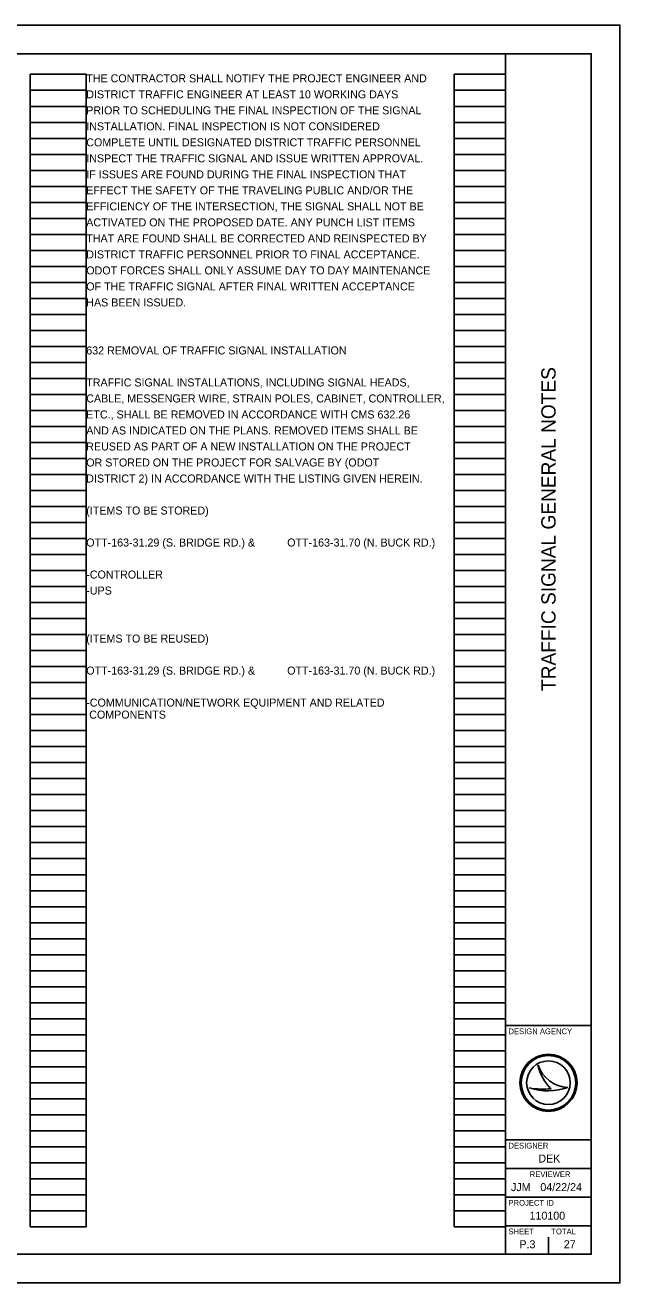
# Model space of a CAD drawing. Extents: x 26.5 to 76, y -1.6 to 20.4.
# Drawn here: x 65.56 to 75.97, y -1.61 to 20.39 of the extents above; entities that cross this region are included whole.
import ezdxf

# ---------------------------------------------------------------- set-up
doc = ezdxf.new("R2010")
doc.units = 0
for name, color, linetype in [('SH_Border', 7, 'Continuous'), ('SH_Cut_Line', 7, 'Continuous'), ('SH_Data', 7, 'Continuous'), ('SH_Text', 7, 'Continuous')]:
    doc.layers.add(name, color=color, linetype=linetype)

msp = doc.modelspace()

# ---------------------------------------------------------------- linework, layer by layer
at = {"layer": 'SH_Border'}
for p, q in [((73.967, -1.109), (73.967, 19.891)), ((73.967, 2.891), (75.467, 2.891)), ((73.967, 0.891), (75.467, 0.891)), ((73.967, 0.391), (75.467, 0.391)), ((73.967, -0.109), (75.467, -0.109)), ((73.967, -0.609), (75.467, -0.609))]:
    msp.add_line(p, q, dxfattribs=at)
msp.add_lwpolyline([(43.467, 19.891), (75.467, 19.891), (75.467, -1.109), (43.467, -1.109)], close=True, dxfattribs=at)
at = {"layer": 'SH_Cut_Line'}
msp.add_lwpolyline([(41.967, -1.609), (75.967, -1.609), (75.967, 20.391), (41.967, 20.391)], close=True, dxfattribs=at)
at = {"layer": 'SH_Data'}
for p, q in [((65.647, -0.629), (65.647, 19.531)), ((65.647, 19.531), (66.627, 19.531)), ((66.627, -0.629), (66.627, 19.531)), ((73.067, -0.629), (73.067, 19.531)), ((73.067, 19.531), (73.967, 19.531)), ((73.967, -0.629), (73.967, 19.531)), ((65.647, 19.251), (66.627, 19.251)), ((73.067, 19.251), (73.967, 19.251)), ((65.647, 18.971), (66.627, 18.971)), ((73.067, 18.971), (73.967, 18.971)), ((65.647, 18.691), (66.627, 18.691)), ((73.067, 18.691), (73.967, 18.691)), ((65.647, 18.411), (66.627, 18.411)), ((73.067, 18.411), (73.967, 18.411)), ((65.647, 18.131), (66.627, 18.131)), ((73.067, 18.131), (73.967, 18.131)), ((65.647, 17.851), (66.627, 17.851)), ((73.067, 17.851), (73.967, 17.851)), ((65.647, 17.571), (66.627, 17.571)), ((73.067, 17.571), (73.967, 17.571)), ((65.647, 17.291), (66.627, 17.291)), ((73.067, 17.291), (73.967, 17.291)), ((65.647, 17.011), (66.627, 17.011)), ((73.067, 17.011), (73.967, 17.011)), ((65.647, 16.731), (66.627, 16.731)), ((73.067, 16.731), (73.967, 16.731)), ((65.647, 16.451), (66.627, 16.451)), ((73.067, 16.451), (73.967, 16.451)), ((65.647, 16.171), (66.627, 16.171)), ((73.067, 16.171), (73.967, 16.171)), ((65.647, 15.891), (66.627, 15.891)), ((73.067, 15.891), (73.967, 15.891)), ((65.647, 15.611), (66.627, 15.611)), ((73.067, 15.611), (73.967, 15.611)), ((65.647, 15.331), (66.627, 15.331)), ((73.067, 15.331), (73.967, 15.331)), ((65.647, 15.051), (66.627, 15.051)), ((73.067, 15.051), (73.967, 15.051)), ((65.647, 14.771), (66.627, 14.771)), ((73.067, 14.771), (73.967, 14.771)), ((65.647, 14.491), (66.627, 14.491)), ((73.067, 14.491), (73.967, 14.491)), ((65.647, 14.211), (66.627, 14.211)), ((73.067, 14.211), (73.967, 14.211)), ((65.647, 13.931), (66.627, 13.931)), ((73.067, 13.931), (73.967, 13.931)), ((65.647, 13.651), (66.627, 13.651)), ((73.067, 13.651), (73.967, 13.651)), ((65.647, 13.371), (66.627, 13.371)), ((73.067, 13.371), (73.967, 13.371)), ((65.647, 13.091), (66.627, 13.091)), ((73.067, 13.091), (73.967, 13.091)), ((65.647, 12.811), (66.627, 12.811)), ((73.067, 12.811), (73.967, 12.811)), ((65.647, 12.531), (66.627, 12.531)), ((73.067, 12.531), (73.967, 12.531)), ((65.647, 12.251), (66.627, 12.251)), ((73.067, 12.251), (73.967, 12.251)), ((65.647, 11.971), (66.627, 11.971)), ((73.067, 11.971), (73.967, 11.971)), ((65.647, 11.691), (66.627, 11.691)), ((73.067, 11.691), (73.967, 11.691)), ((65.647, 11.411), (66.627, 11.411)), ((73.067, 11.411), (73.967, 11.411)), ((65.647, 11.131), (66.627, 11.131)), ((73.067, 11.131), (73.967, 11.131)), ((65.647, 10.851), (66.627, 10.851)), ((73.067, 10.851), (73.967, 10.851)), ((65.647, 10.571), (66.627, 10.571)), ((73.067, 10.571), (73.967, 10.571)), ((65.647, 10.291), (66.627, 10.291)), ((73.067, 10.291), (73.967, 10.291)), ((65.647, 10.011), (66.627, 10.011)), ((73.067, 10.011), (73.967, 10.011)), ((65.647, 9.731), (66.627, 9.731)), ((73.067, 9.731), (73.967, 9.731)), ((65.647, 9.451), (66.627, 9.451)), ((73.067, 9.451), (73.967, 9.451)), ((65.647, 9.171), (66.627, 9.171)), ((73.067, 9.171), (73.967, 9.171)), ((65.647, 8.891), (66.627, 8.891)), ((73.067, 8.891), (73.967, 8.891)), ((65.647, 8.611), (66.627, 8.611)), ((73.067, 8.611), (73.967, 8.611)), ((65.647, 8.331), (66.627, 8.331)), ((73.067, 8.331), (73.967, 8.331)), ((65.647, 8.051), (66.627, 8.051)), ((73.067, 8.051), (73.967, 8.051)), ((65.647, 7.771), (66.627, 7.771)), ((73.067, 7.771), (73.967, 7.771)), ((65.647, 7.491), (66.627, 7.491)), ((73.067, 7.491), (73.967, 7.491)), ((65.647, 7.211), (66.627, 7.211)), ((73.067, 7.211), (73.967, 7.211)), ((65.647, 6.931), (66.627, 6.931)), ((73.067, 6.931), (73.967, 6.931)), ((65.647, 6.651), (66.627, 6.651)), ((73.067, 6.651), (73.967, 6.651)), ((65.647, 6.371), (66.627, 6.371)), ((73.067, 6.371), (73.967, 6.371)), ((65.647, 6.091), (66.627, 6.091)), ((73.067, 6.091), (73.967, 6.091)), ((65.647, 5.811), (66.627, 5.811)), ((73.067, 5.811), (73.967, 5.811)), ((65.647, 5.531), (66.627, 5.531)), ((73.067, 5.531), (73.967, 5.531)), ((65.647, 5.251), (66.627, 5.251)), ((73.067, 5.251), (73.967, 5.251)), ((65.647, 4.971), (66.627, 4.971)), ((73.067, 4.971), (73.967, 4.971)), ((65.647, 4.691), (66.627, 4.691)), ((73.067, 4.691), (73.967, 4.691)), ((65.647, 4.411), (66.627, 4.411)), ((73.067, 4.411), (73.967, 4.411)), ((65.647, 4.131), (66.627, 4.131)), ((73.067, 4.131), (73.967, 4.131)), ((65.647, 3.851), (66.627, 3.851)), ((73.067, 3.851), (73.967, 3.851)), ((65.647, 3.571), (66.627, 3.571)), ((73.067, 3.571), (73.967, 3.571)), ((65.647, 3.291), (66.627, 3.291)), ((73.067, 3.291), (73.967, 3.291)), ((65.647, 3.011), (66.627, 3.011)), ((73.067, 3.011), (73.967, 3.011)), ((65.647, 2.731), (66.627, 2.731)), ((73.067, 2.731), (73.967, 2.731)), ((65.647, 2.451), (66.627, 2.451)), ((73.067, 2.451), (73.967, 2.451)), ((74.534, 2.201), (74.534, 2.201)), ((65.647, 2.171), (66.627, 2.171)), ((73.067, 2.171), (73.967, 2.171)), ((65.647, 1.891), (66.627, 1.891)), ((73.067, 1.891), (73.967, 1.891)), ((74.384, 1.801), (74.384, 1.801)), ((74.717, 1.891), (74.717, 1.891)), ((75.054, 1.81), (75.054, 1.81)), ((65.647, 1.611), (66.627, 1.611)), ((73.067, 1.611), (73.967, 1.611)), ((65.647, 1.331), (66.627, 1.331)), ((73.067, 1.331), (73.967, 1.331)), ((65.647, 1.051), (66.627, 1.051)), ((73.067, 1.051), (73.967, 1.051)), ((65.647, 0.771), (66.627, 0.771)), ((73.067, 0.771), (73.967, 0.771)), ((65.647, 0.491), (66.627, 0.491)), ((73.067, 0.491), (73.967, 0.491)), ((65.647, 0.211), (66.627, 0.211)), ((73.067, 0.211), (73.967, 0.211)), ((65.647, -0.069), (66.627, -0.069)), ((73.067, -0.069), (73.967, -0.069)), ((65.647, -0.349), (66.627, -0.349)), ((73.067, -0.349), (73.967, -0.349)), ((65.647, -0.629), (66.627, -0.629)), ((73.067, -0.629), (73.967, -0.629)), ((74.717, -1.109), (74.717, -0.809)), ((74.342, -0.934), (74.342, -0.934))]:
    msp.add_line(p, q, dxfattribs=at)
for radius in [0.5, 0.477, 0.477, 0.382]:
    msp.add_circle((74.717, 1.891), radius, dxfattribs=at)
for centre, radius, start, end in [((75.083, 2.389), 0.58, 198.9257, 198.9319), ((75.313, 2.361), 0.796, 191.6379, 191.6421), ((75.083, 2.389), 0.58, 198.9319, 267.1657), ((75.313, 2.361), 0.796, 191.6421, 226.0947), ((74.706, 2.761), 1.013, 251.4576, 290.0832), ((74.615, 3.045), 1.266, 259.4964, 259.4995), ((74.706, 2.761), 1.013, 251.4527, 251.4576), ((74.615, 3.045), 1.266, 259.4995, 276.6672)]:
    msp.add_arc(centre, radius, start, end, dxfattribs=at)

# ---------------------------------------------------------------- texts
msp.add_text('TRAFFIC SIGNAL GENERAL NOTES', height=0.25, rotation=90, dxfattribs=at).set_placement((74.842, 8.744))
for s, height, p in [('DESIGN AGENCY', 0.1, (74.017, 2.741)), ('DESIGNER', 0.1, (74.017, 0.741)), ('DEK', 0.14, (74.54, 0.496)), ('REVIEWER', 0.1, (74.389, 0.241)), ('JJM', 0.14, (74.061, -0.004)), ('04/22/24', 0.14, (74.575, -0.004)), ('PROJECT ID', 0.1, (74.017, -0.259)), ('110100', 0.14, (74.385, -0.504)), ('SHEET', 0.1, (74.017, -0.759)), ('TOTAL', 0.1, (74.767, -0.759)), ('P.3', 0.14, (74.208, -1.004)), ('27', 0.14, (74.985, -1.004))]:
    msp.add_text(s, height=height, dxfattribs=at).set_placement(p)
at = {"layer": 'SH_Text'}
for s, p in [('THE CONTRACTOR SHALL NOTIFY THE PROJECT ENGINEER AND', (66.627, 19.391)), ('DISTRICT TRAFFIC ENGINEER AT LEAST 10 WORKING DAYS', (66.627, 19.111)), ('PRIOR TO SCHEDULING THE FINAL INSPECTION OF THE SIGNAL', (66.627, 18.831)), ('INSTALLATION. FINAL INSPECTION IS NOT CONSIDERED', (66.627, 18.551)), ('COMPLETE UNTIL DESIGNATED DISTRICT TRAFFIC PERSONNEL', (66.627, 18.271)), ('INSPECT THE TRAFFIC SIGNAL AND ISSUE WRITTEN APPROVAL.', (66.627, 17.991)), ('IF ISSUES ARE FOUND DURING THE FINAL INSPECTION THAT', (66.627, 17.711)), ('EFFECT THE SAFETY OF THE TRAVELING PUBLIC AND/OR THE', (66.627, 17.431)), ('EFFICIENCY OF THE INTERSECTION, THE SIGNAL SHALL NOT BE', (66.627, 17.151)), ('ACTIVATED ON THE PROPOSED DATE. ANY PUNCH LIST ITEMS', (66.627, 16.871)), ('THAT ARE FOUND SHALL BE CORRECTED AND REINSPECTED BY', (66.627, 16.591)), ('DISTRICT TRAFFIC PERSONNEL PRIOR TO FINAL ACCEPTANCE.', (66.627, 16.311)), ('ODOT FORCES SHALL ONLY ASSUME DAY TO DAY MAINTENANCE', (66.627, 16.031)), ('OF THE TRAFFIC SIGNAL AFTER FINAL WRITTEN ACCEPTANCE', (66.627, 15.751)), ('HAS BEEN ISSUED.', (66.627, 15.471)), ('632 REMOVAL OF TRAFFIC SIGNAL INSTALLATION', (66.627, 14.631)), ('TRAFFIC SIGNAL INSTALLATIONS, INCLUDING SIGNAL HEADS,', (66.627, 14.071)), ('CABLE, MESSENGER WIRE, STRAIN POLES, CABINET, CONTROLLER,', (66.627, 13.791)), ('ETC., SHALL BE REMOVED IN ACCORDANCE WITH CMS 632.26', (66.627, 13.511)), ('AND AS INDICATED ON THE PLANS. REMOVED ITEMS SHALL BE', (66.627, 13.231)), ('REUSED AS PART OF A NEW INSTALLATION ON THE PROJECT', (66.627, 12.951)), ('OR STORED ON THE PROJECT FOR SALVAGE BY (ODOT', (66.627, 12.671)), ('DISTRICT 2) IN ACCORDANCE WITH THE LISTING GIVEN HEREIN.', (66.627, 12.391)), ('(ITEMS TO BE STORED)', (66.627, 11.831)), ('OTT-163-31.29 (S. BRIDGE RD.) & ', (66.627, 11.271)), ('OTT-163-31.70 (N. BUCK RD.)', (70.144, 11.271)), ('-CONTROLLER', (66.627, 10.711)), ('-UPS', (66.627, 10.431)), ('(ITEMS TO BE REUSED)', (66.627, 9.591)), ('OTT-163-31.29 (S. BRIDGE RD.) & ', (66.627, 9.031)), ('OTT-163-31.70 (N. BUCK RD.)', (70.144, 9.031)), ('-COMMUNICATION/NETWORK EQUIPMENT AND RELATED ', (66.627, 8.471)), (' COMPONENTS', (66.627, 8.261))]:
    msp.add_text(s, height=0.14, dxfattribs=at).set_placement(p)

doc.saveas('drawing.dxf')
